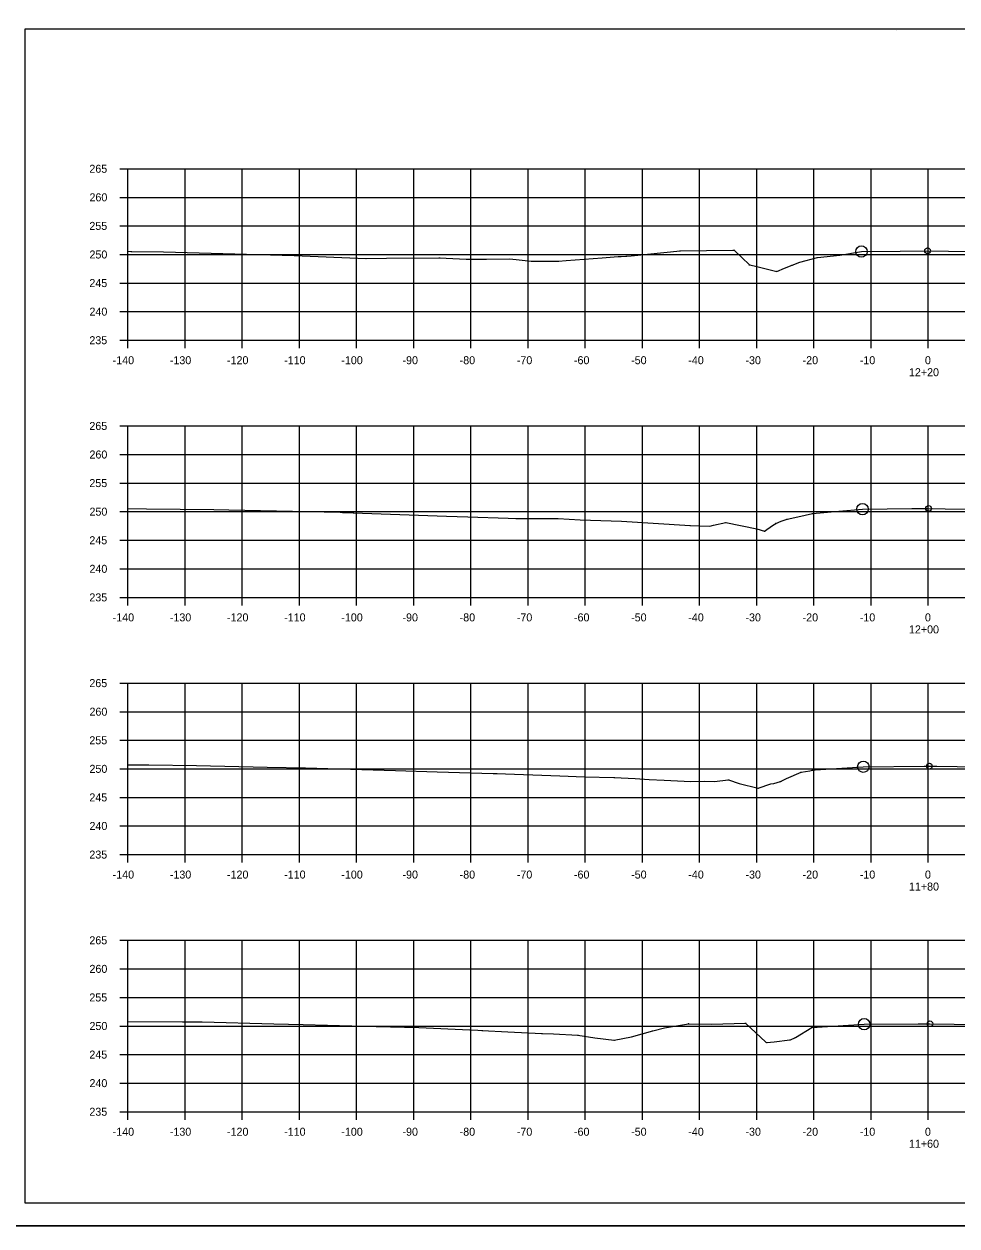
# Model space of a CAD drawing. Extents: x 1300404 to 1323571, y 234004 to 252077.
# Drawn here: x 1315559.1 to 1315722.3, y 243835.2 to 244045.5 of the extents above; entities that cross this region are included whole.
import ezdxf

# ---------------------------------------------------------------- set-up
doc = ezdxf.new("R2010")
doc.units = 0
for name, color, linetype in [('Default', 7, 'Continuous'), ('R_Axis', 7, 'Continuous'), ('R_Axis Annot', 7, 'Continuous'), ('R_Border', 7, 'Continuous'), ('R_Draft', 7, 'Continuous'), ('R_Exist Surface', 7, 'Continuous'), ('R_Grid', 7, 'Continuous'), ('R_No Plot', 7, 'Continuous')]:
    doc.layers.add(name, color=color, linetype=linetype)

msp = doc.modelspace()

# ---------------------------------------------------------------- linework, layer by layer
at = {"layer": 'Default'}
for p, q in [((1315559.28, 244044.61), (1315875.46, 244044.61)), ((1315559.28, 243839.15), (1315559.28, 244044.61)), ((1315875.46, 243839.15), (1315559.28, 243839.15))]:
    msp.add_line(p, q, dxfattribs=at)
at = {"layer": 'R_Axis'}
for p, q in [((1315575.88, 244020.15), (1315577.28, 244020.15)), ((1315577.28, 243990.15), (1315577.28, 244020.15)), ((1315575.88, 244015.15), (1315577.28, 244015.15)), ((1315575.88, 244010.15), (1315577.28, 244010.15)), ((1315575.88, 244005.15), (1315577.28, 244005.15)), ((1315575.88, 244000.15), (1315577.28, 244000.15)), ((1315575.88, 243995.15), (1315577.28, 243995.15)), ((1315575.88, 243990.15), (1315577.28, 243990.15)), ((1315577.28, 243990.15), (1315857.28, 243990.15)), ((1315577.28, 243988.75), (1315577.28, 243990.15)), ((1315587.28, 243988.75), (1315587.28, 243990.15)), ((1315597.28, 243988.75), (1315597.28, 243990.15)), ((1315607.28, 243988.75), (1315607.28, 243990.15)), ((1315617.28, 243988.75), (1315617.28, 243990.15)), ((1315627.28, 243988.75), (1315627.28, 243990.15)), ((1315637.28, 243988.75), (1315637.28, 243990.15)), ((1315647.28, 243988.75), (1315647.28, 243990.15)), ((1315657.28, 243988.75), (1315657.28, 243990.15)), ((1315667.28, 243988.75), (1315667.28, 243990.15)), ((1315677.28, 243988.75), (1315677.28, 243990.15)), ((1315687.28, 243988.75), (1315687.28, 243990.15)), ((1315697.28, 243988.75), (1315697.28, 243990.15)), ((1315707.28, 243988.75), (1315707.28, 243990.15)), ((1315717.28, 243988.75), (1315717.28, 243990.15)), ((1315575.88, 243975.15), (1315577.28, 243975.15)), ((1315577.28, 243945.15), (1315577.28, 243975.15)), ((1315575.88, 243970.15), (1315577.28, 243970.15)), ((1315575.88, 243965.15), (1315577.28, 243965.15)), ((1315575.88, 243960.15), (1315577.28, 243960.15)), ((1315575.88, 243955.15), (1315577.28, 243955.15)), ((1315575.88, 243950.15), (1315577.28, 243950.15)), ((1315575.88, 243945.15), (1315577.28, 243945.15)), ((1315577.28, 243945.15), (1315857.28, 243945.15)), ((1315577.28, 243943.75), (1315577.28, 243945.15)), ((1315587.28, 243943.75), (1315587.28, 243945.15)), ((1315597.28, 243943.75), (1315597.28, 243945.15)), ((1315607.28, 243943.75), (1315607.28, 243945.15)), ((1315617.28, 243943.75), (1315617.28, 243945.15)), ((1315627.28, 243943.75), (1315627.28, 243945.15)), ((1315637.28, 243943.75), (1315637.28, 243945.15)), ((1315647.28, 243943.75), (1315647.28, 243945.15)), ((1315657.28, 243943.75), (1315657.28, 243945.15)), ((1315667.28, 243943.75), (1315667.28, 243945.15)), ((1315677.28, 243943.75), (1315677.28, 243945.15)), ((1315687.28, 243943.75), (1315687.28, 243945.15)), ((1315697.28, 243943.75), (1315697.28, 243945.15)), ((1315707.28, 243943.75), (1315707.28, 243945.15)), ((1315717.28, 243943.75), (1315717.28, 243945.15)), ((1315575.88, 243930.15), (1315577.28, 243930.15)), ((1315577.28, 243900.15), (1315577.28, 243930.15)), ((1315575.88, 243925.15), (1315577.28, 243925.15)), ((1315575.88, 243920.15), (1315577.28, 243920.15)), ((1315575.88, 243915.15), (1315577.28, 243915.15)), ((1315575.88, 243910.15), (1315577.28, 243910.15)), ((1315575.88, 243905.15), (1315577.28, 243905.15)), ((1315575.88, 243900.15), (1315577.28, 243900.15)), ((1315577.28, 243900.15), (1315857.28, 243900.15)), ((1315577.28, 243898.75), (1315577.28, 243900.15)), ((1315587.28, 243898.75), (1315587.28, 243900.15)), ((1315597.28, 243898.75), (1315597.28, 243900.15)), ((1315607.28, 243898.75), (1315607.28, 243900.15)), ((1315617.28, 243898.75), (1315617.28, 243900.15)), ((1315627.28, 243898.75), (1315627.28, 243900.15)), ((1315637.28, 243898.75), (1315637.28, 243900.15)), ((1315647.28, 243898.75), (1315647.28, 243900.15)), ((1315657.28, 243898.75), (1315657.28, 243900.15)), ((1315667.28, 243898.75), (1315667.28, 243900.15)), ((1315677.28, 243898.75), (1315677.28, 243900.15)), ((1315687.28, 243898.75), (1315687.28, 243900.15)), ((1315697.28, 243898.75), (1315697.28, 243900.15)), ((1315707.28, 243898.75), (1315707.28, 243900.15)), ((1315717.28, 243898.75), (1315717.28, 243900.15)), ((1315575.88, 243885.15), (1315577.28, 243885.15)), ((1315577.28, 243855.15), (1315577.28, 243885.15)), ((1315575.88, 243880.15), (1315577.28, 243880.15)), ((1315575.88, 243875.15), (1315577.28, 243875.15)), ((1315575.88, 243870.15), (1315577.28, 243870.15)), ((1315575.88, 243865.15), (1315577.28, 243865.15)), ((1315575.88, 243860.15), (1315577.28, 243860.15)), ((1315575.88, 243855.15), (1315577.28, 243855.15)), ((1315577.28, 243855.15), (1315857.28, 243855.15)), ((1315577.28, 243853.75), (1315577.28, 243855.15)), ((1315587.28, 243853.75), (1315587.28, 243855.15)), ((1315597.28, 243853.75), (1315597.28, 243855.15)), ((1315607.28, 243853.75), (1315607.28, 243855.15)), ((1315617.28, 243853.75), (1315617.28, 243855.15)), ((1315627.28, 243853.75), (1315627.28, 243855.15)), ((1315637.28, 243853.75), (1315637.28, 243855.15)), ((1315647.28, 243853.75), (1315647.28, 243855.15)), ((1315657.28, 243853.75), (1315657.28, 243855.15)), ((1315667.28, 243853.75), (1315667.28, 243855.15)), ((1315677.28, 243853.75), (1315677.28, 243855.15)), ((1315687.28, 243853.75), (1315687.28, 243855.15)), ((1315697.28, 243853.75), (1315697.28, 243855.15)), ((1315707.28, 243853.75), (1315707.28, 243855.15)), ((1315717.28, 243853.75), (1315717.28, 243855.15))]:
    msp.add_line(p, q, dxfattribs=at)
at = {"layer": 'R_Border'}
for p, q in [((1315711.8, 244044.35), (1315711.8, 244044.35)), ((1315711.8, 244044.35), (1315711.8, 244044.35)), ((1315559.28, 243839.15), (1315559.28, 243839.15))]:
    msp.add_line(p, q, dxfattribs=at)
at = {"layer": 'R_Draft'}
for points in [[(1315577.86, 244005.73), (1315577.91, 244005.63), (1315577.81, 244005.63)], [(1315618.92, 244004.49), (1315618.97, 244004.39), (1315618.87, 244004.39)], [(1315631.78, 244004.63), (1315631.83, 244004.53), (1315631.73, 244004.53)], [(1315664.49, 244004.9), (1315664.54, 244004.8), (1315664.44, 244004.8)], [(1315673.91, 244005.82), (1315673.96, 244005.72), (1315673.86, 244005.72)], [(1315683.31, 244005.97), (1315683.36, 244005.87), (1315683.26, 244005.87)], [(1315697.89, 244004.69), (1315697.94, 244004.59), (1315697.84, 244004.59)], [(1315647.86, 244004.04), (1315647.91, 244003.94), (1315647.81, 244003.94)], [(1315652.61, 244004.05), (1315652.66, 244003.95), (1315652.56, 244003.95)], [(1315686.01, 244003.39), (1315686.06, 244003.29), (1315685.96, 244003.29)], [(1315693.49, 244003.33), (1315693.54, 244003.23), (1315693.44, 244003.23)], [(1315690.79, 244002.25), (1315690.84, 244002.15), (1315690.74, 244002.15)], [(1315616.69, 243960.02), (1315616.74, 243959.92), (1315616.64, 243959.92)], [(1315646.06, 243959.01), (1315646.11, 243958.91), (1315646.01, 243958.91)], [(1315681.86, 243958.28), (1315681.91, 243958.18), (1315681.81, 243958.18)], [(1315692.6, 243958.89), (1315692.65, 243958.79), (1315692.55, 243958.79)], [(1315697.02, 243959.85), (1315697.07, 243959.75), (1315696.97, 243959.75)], [(1315675.64, 243957.75), (1315675.69, 243957.65), (1315675.59, 243957.65)], [(1315688.63, 243956.78), (1315688.68, 243956.68), (1315688.58, 243956.68)], [(1315690.64, 243958.15), (1315690.69, 243958.05), (1315690.59, 243958.05)], [(1315641.75, 243914.37), (1315641.8, 243914.27), (1315641.7, 243914.27)], [(1315695.04, 243914.63), (1315695.09, 243914.53), (1315694.99, 243914.53)], [(1315697.02, 243914.98), (1315697.07, 243914.88), (1315696.97, 243914.88)], [(1315662.33, 243913.7), (1315662.38, 243913.6), (1315662.28, 243913.6)], [(1315682.35, 243913.29), (1315682.4, 243913.19), (1315682.3, 243913.19)], [(1315691.46, 243912.99), (1315691.51, 243912.89), (1315691.41, 243912.89)], [(1315687.53, 243911.79), (1315687.58, 243911.69), (1315687.48, 243911.69)], [(1315675.36, 243870.61), (1315675.41, 243870.51), (1315675.31, 243870.51)], [(1315685.3, 243870.69), (1315685.35, 243870.59), (1315685.25, 243870.59)], [(1315696.92, 243869.93), (1315696.97, 243869.83), (1315696.87, 243869.83)], [(1315639.25, 243869.43), (1315639.3, 243869.33), (1315639.2, 243869.33)], [(1315649.68, 243868.87), (1315649.73, 243868.77), (1315649.63, 243868.77)], [(1315656, 243868.6), (1315656.05, 243868.5), (1315655.95, 243868.5)], [(1315669.08, 243869.36), (1315669.13, 243869.26), (1315669.03, 243869.26)], [(1315693.07, 243867.76), (1315693.12, 243867.66), (1315693.02, 243867.66)], [(1315694.08, 243868.18), (1315694.13, 243868.08), (1315694.03, 243868.08)], [(1315662.34, 243867.7), (1315662.39, 243867.6), (1315662.29, 243867.6)], [(1315689.05, 243867.29), (1315689.1, 243867.19), (1315689, 243867.19)]]:
    msp.add_lwpolyline(points, close=True, dxfattribs=at)
at = {"layer": 'R_Exist Surface'}
for points in [[(1315577.28, 244005.74), (1315577.86, 244005.68), (1315583.52, 244005.59), (1315606.38, 244004.98), (1315618.92, 244004.44), (1315622.54, 244004.5), (1315631.78, 244004.58), (1315636.45, 244004.34), (1315639.98, 244004.33), (1315644.08, 244004.37), (1315647.86, 244003.99), (1315651.37, 244004.01), (1315652.61, 244004), (1315653.92, 244004.1), (1315660.25, 244004.57), (1315663.05, 244004.77), (1315663.56, 244004.78), (1315664.49, 244004.85), (1315665.29, 244004.93), (1315673.91, 244005.77), (1315683.08, 244005.92), (1315683.22, 244005.92), (1315683.31, 244005.92), (1315683.35, 244005.91), (1315686.01, 244003.34), (1315686.83, 244003.17), (1315690.79, 244002.2), (1315692.14, 244002.74), (1315693.49, 244003.28), (1315694.83, 244003.79), (1315697.89, 244004.64), (1315701.8, 244005.05), (1315705.6, 244005.66), (1315712.38, 244005.74), (1315717.17, 244005.81), (1315724.49, 244005.7)], [(1315577.28, 243960.72), (1315580.53, 243960.67), (1315592.3, 243960.51), (1315594.95, 243960.45), (1315614.41, 243960.05), (1315614.84, 243960.03), (1315616.69, 243959.97), (1315633, 243959.36), (1315636.75, 243959.26), (1315643.81, 243959), (1315645.11, 243958.97), (1315646.06, 243958.96), (1315652.54, 243958.94), (1315656.39, 243958.73), (1315663.65, 243958.46), (1315675.64, 243957.7), (1315677.18, 243957.65), (1315679.06, 243957.6), (1315679.72, 243957.77), (1315681.86, 243958.23), (1315687.3, 243957.16), (1315688.63, 243956.73), (1315690.03, 243957.7), (1315690.64, 243958.1), (1315691.57, 243958.46), (1315692.6, 243958.84), (1315694.45, 243959.22), (1315697.02, 243959.8), (1315701.65, 243960.26), (1315705.79, 243960.58), (1315714.41, 243960.68), (1315717.35, 243960.71), (1315720.25, 243960.67), (1315729.39, 243960.54)], [(1315577.28, 243915.87), (1315580.94, 243915.87), (1315589.26, 243915.76), (1315601.65, 243915.45), (1315608.36, 243915.31), (1315624.07, 243914.88), (1315631.4, 243914.64), (1315641.17, 243914.33), (1315641.75, 243914.32), (1315652.86, 243913.9), (1315657.17, 243913.78), (1315662.33, 243913.65), (1315666.01, 243913.44), (1315668.45, 243913.3), (1315671.1, 243913.18), (1315675.76, 243912.91), (1315678.21, 243912.98), (1315679.85, 243912.93), (1315682.35, 243913.24), (1315684.23, 243912.61), (1315687.53, 243911.74), (1315689.73, 243912.53), (1315690.25, 243912.56), (1315691.46, 243912.94), (1315692.48, 243913.45), (1315695.04, 243914.58), (1315696.57, 243914.83), (1315697.02, 243914.93), (1315697.52, 243914.97), (1315705.93, 243915.52), (1315716.6, 243915.61), (1315717.48, 243915.62), (1315718.79, 243915.6), (1315729.5, 243915.44)], [(1315577.28, 243870.96), (1315586.83, 243870.87), (1315590.24, 243870.88), (1315602.82, 243870.56), (1315607.92, 243870.42), (1315620.72, 243870.07), (1315628.18, 243869.87), (1315637.1, 243869.46), (1315638.5, 243869.4), (1315639.25, 243869.38), (1315643.76, 243869.16), (1315649.68, 243868.82), (1315651.74, 243868.77), (1315656, 243868.55), (1315658.97, 243868.06), (1315662.34, 243867.65), (1315665.4, 243868.28), (1315669.08, 243869.31), (1315671.17, 243869.81), (1315675.36, 243870.56), (1315679.37, 243870.46), (1315685.3, 243870.64), (1315688.9, 243867.34), (1315689.05, 243867.24), (1315690.34, 243867.39), (1315693.07, 243867.71), (1315693.19, 243867.75), (1315694.08, 243868.13), (1315696.91, 243869.87), (1315696.92, 243869.88), (1315696.95, 243869.88), (1315706.07, 243870.46), (1315715.51, 243870.53), (1315717.59, 243870.55), (1315721.8, 243870.48), (1315729.53, 243870.36)]]:
    msp.add_lwpolyline(points, dxfattribs=at)
at = {"layer": 'R_Grid'}
for p, q in [((1315577.28, 244020.15), (1315857.28, 244020.15)), ((1315577.28, 243990.15), (1315577.28, 244020.15)), ((1315587.28, 243990.15), (1315587.28, 244020.15)), ((1315597.28, 243990.15), (1315597.28, 244020.15)), ((1315607.28, 243990.15), (1315607.28, 244020.15)), ((1315617.28, 243990.15), (1315617.28, 244020.15)), ((1315627.28, 243990.15), (1315627.28, 244020.15)), ((1315637.28, 243990.15), (1315637.28, 244020.15)), ((1315647.28, 243990.15), (1315647.28, 244020.15)), ((1315657.28, 243990.15), (1315657.28, 244020.15)), ((1315667.28, 243990.15), (1315667.28, 244020.15)), ((1315677.28, 243990.15), (1315677.28, 244020.15)), ((1315687.28, 243990.15), (1315687.28, 244020.15)), ((1315697.28, 243990.15), (1315697.28, 244020.15)), ((1315707.28, 243990.15), (1315707.28, 244020.15)), ((1315717.28, 243990.15), (1315717.28, 244020.15)), ((1315577.28, 244015.15), (1315857.28, 244015.15)), ((1315577.28, 244010.15), (1315857.28, 244010.15)), ((1315577.28, 244005.15), (1315857.28, 244005.15)), ((1315577.28, 244000.15), (1315857.28, 244000.15)), ((1315577.28, 243995.15), (1315857.28, 243995.15)), ((1315577.28, 243990.15), (1315857.28, 243990.15)), ((1315577.28, 243975.15), (1315857.28, 243975.15)), ((1315577.28, 243945.15), (1315577.28, 243975.15)), ((1315587.28, 243945.15), (1315587.28, 243975.15)), ((1315597.28, 243945.15), (1315597.28, 243975.15)), ((1315607.28, 243945.15), (1315607.28, 243975.15)), ((1315617.28, 243945.15), (1315617.28, 243975.15)), ((1315627.28, 243945.15), (1315627.28, 243975.15)), ((1315637.28, 243945.15), (1315637.28, 243975.15)), ((1315647.28, 243945.15), (1315647.28, 243975.15)), ((1315657.28, 243945.15), (1315657.28, 243975.15)), ((1315667.28, 243945.15), (1315667.28, 243975.15)), ((1315677.28, 243945.15), (1315677.28, 243975.15)), ((1315687.28, 243945.15), (1315687.28, 243975.15)), ((1315697.28, 243945.15), (1315697.28, 243975.15)), ((1315707.28, 243945.15), (1315707.28, 243975.15)), ((1315717.28, 243945.15), (1315717.28, 243975.15)), ((1315577.28, 243970.15), (1315857.28, 243970.15)), ((1315577.28, 243965.15), (1315857.28, 243965.15)), ((1315577.28, 243960.15), (1315857.28, 243960.15)), ((1315577.28, 243955.15), (1315857.28, 243955.15)), ((1315577.28, 243950.15), (1315857.28, 243950.15)), ((1315577.28, 243945.15), (1315857.28, 243945.15)), ((1315577.28, 243930.15), (1315857.28, 243930.15)), ((1315577.28, 243900.15), (1315577.28, 243930.15)), ((1315587.28, 243900.15), (1315587.28, 243930.15)), ((1315597.28, 243900.15), (1315597.28, 243930.15)), ((1315607.28, 243900.15), (1315607.28, 243930.15)), ((1315617.28, 243900.15), (1315617.28, 243930.15)), ((1315627.28, 243900.15), (1315627.28, 243930.15)), ((1315637.28, 243900.15), (1315637.28, 243930.15)), ((1315647.28, 243900.15), (1315647.28, 243930.15)), ((1315657.28, 243900.15), (1315657.28, 243930.15)), ((1315667.28, 243900.15), (1315667.28, 243930.15)), ((1315677.28, 243900.15), (1315677.28, 243930.15)), ((1315687.28, 243900.15), (1315687.28, 243930.15)), ((1315697.28, 243900.15), (1315697.28, 243930.15)), ((1315707.28, 243900.15), (1315707.28, 243930.15)), ((1315717.28, 243900.15), (1315717.28, 243930.15)), ((1315577.28, 243925.15), (1315857.28, 243925.15)), ((1315577.28, 243920.15), (1315857.28, 243920.15)), ((1315577.28, 243915.15), (1315857.28, 243915.15)), ((1315577.28, 243910.15), (1315857.28, 243910.15)), ((1315577.28, 243905.15), (1315857.28, 243905.15)), ((1315577.28, 243900.15), (1315857.28, 243900.15)), ((1315577.28, 243885.15), (1315857.28, 243885.15)), ((1315577.28, 243855.15), (1315577.28, 243885.15)), ((1315587.28, 243855.15), (1315587.28, 243885.15)), ((1315597.28, 243855.15), (1315597.28, 243885.15)), ((1315607.28, 243855.15), (1315607.28, 243885.15)), ((1315617.28, 243855.15), (1315617.28, 243885.15)), ((1315627.28, 243855.15), (1315627.28, 243885.15)), ((1315637.28, 243855.15), (1315637.28, 243885.15)), ((1315647.28, 243855.15), (1315647.28, 243885.15)), ((1315657.28, 243855.15), (1315657.28, 243885.15)), ((1315667.28, 243855.15), (1315667.28, 243885.15)), ((1315677.28, 243855.15), (1315677.28, 243885.15)), ((1315687.28, 243855.15), (1315687.28, 243885.15)), ((1315697.28, 243855.15), (1315697.28, 243885.15)), ((1315707.28, 243855.15), (1315707.28, 243885.15)), ((1315717.28, 243855.15), (1315717.28, 243885.15)), ((1315577.28, 243880.15), (1315857.28, 243880.15)), ((1315577.28, 243875.15), (1315857.28, 243875.15)), ((1315577.28, 243870.15), (1315857.28, 243870.15)), ((1315577.28, 243865.15), (1315857.28, 243865.15)), ((1315577.28, 243860.15), (1315857.28, 243860.15)), ((1315577.28, 243855.15), (1315857.28, 243855.15))]:
    msp.add_line(p, q, dxfattribs=at)
at = {"layer": 'R_No Plot'}
msp.add_line((1315546.87, 243835.17), (1315880.21, 243835.17), dxfattribs=at)
for points in [[(1315546.87, 244048.5), (1315880.21, 244048.5), (1315880.21, 243835.16), (1315546.87, 243835.16)], [(1315793.2, 244044.61), (1315793.2, 244034.73), (1315828.93, 244034.73), (1315828.93, 244031.81), (1315852.13, 244031.81), (1315852.13, 244009.69), (1315875.46, 244009.69), (1315875.46, 243839.15), (1315559.28, 243839.15), (1315559.28, 244044.61)]]:
    msp.add_lwpolyline(points, close=True, dxfattribs=at)
for centre, radius in [((1315705.6, 244005.66), 1), ((1315717.17, 244005.81), 0.5), ((1315705.79, 243960.58), 1), ((1315717.35, 243960.71), 0.5), ((1315705.93, 243915.52), 1), ((1315717.48, 243915.62), 0.5), ((1315706.07, 243870.46), 1), ((1315717.59, 243870.55), 0.5)]:
    msp.add_circle(centre, radius, dxfattribs=at)

# ---------------------------------------------------------------- texts
at = {"layer": 'R_Axis'}
for p in [(1315577.28, 243990.15), (1315577.28, 243945.15), (1315577.28, 243900.15), (1315577.28, 243855.15)]:
    msp.add_text('-', height=0.0001, dxfattribs=at).set_placement(p)
at = {"layer": 'R_Axis Annot'}
for s, p in [('265', (1315570.53, 244019.45)), ('260', (1315570.55, 244014.45)), ('255', (1315570.53, 244009.45)), ('250', (1315570.55, 244004.45)), ('245', (1315570.53, 243999.45)), ('240', (1315570.55, 243994.45)), ('235', (1315570.53, 243989.45)), ('-140', (1315574.61, 243985.95)), ('-130', (1315584.61, 243985.95)), ('-120', (1315594.61, 243985.95)), ('-110', (1315604.61, 243985.95)), ('-100', (1315614.61, 243985.95)), ('-90', (1315625.31, 243985.95)), ('-80', (1315635.31, 243985.95)), ('-70', (1315645.31, 243985.95)), ('-60', (1315655.31, 243985.95)), ('-50', (1315665.31, 243985.95)), ('-40', (1315675.31, 243985.95)), ('-30', (1315685.31, 243985.95)), ('-20', (1315695.31, 243985.95)), ('-10', (1315705.31, 243985.95)), ('0', (1315716.71, 243985.95)), ('12+20', (1315713.91, 243983.85)), ('265', (1315570.53, 243974.45)), ('260', (1315570.55, 243969.45)), ('255', (1315570.53, 243964.45)), ('250', (1315570.55, 243959.45)), ('245', (1315570.53, 243954.45)), ('240', (1315570.55, 243949.45)), ('235', (1315570.53, 243944.45)), ('-140', (1315574.61, 243940.95)), ('-130', (1315584.61, 243940.95)), ('-120', (1315594.61, 243940.95)), ('-110', (1315604.61, 243940.95)), ('-100', (1315614.61, 243940.95)), ('-90', (1315625.31, 243940.95)), ('-80', (1315635.31, 243940.95)), ('-70', (1315645.31, 243940.95)), ('-60', (1315655.31, 243940.95)), ('-50', (1315665.31, 243940.95)), ('-40', (1315675.31, 243940.95)), ('-30', (1315685.31, 243940.95)), ('-20', (1315695.31, 243940.95)), ('-10', (1315705.31, 243940.95)), ('0', (1315716.71, 243940.95)), ('12+00', (1315713.91, 243938.85)), ('265', (1315570.53, 243929.45)), ('260', (1315570.55, 243924.45)), ('255', (1315570.53, 243919.45)), ('250', (1315570.55, 243914.45)), ('245', (1315570.53, 243909.45)), ('240', (1315570.55, 243904.45)), ('235', (1315570.53, 243899.45)), ('-140', (1315574.61, 243895.95)), ('-130', (1315584.61, 243895.95)), ('-120', (1315594.61, 243895.95)), ('-110', (1315604.61, 243895.95)), ('-100', (1315614.61, 243895.95)), ('-90', (1315625.31, 243895.95)), ('-80', (1315635.31, 243895.95)), ('-70', (1315645.31, 243895.95)), ('-60', (1315655.31, 243895.95)), ('-50', (1315665.31, 243895.95)), ('-40', (1315675.31, 243895.95)), ('-30', (1315685.31, 243895.95)), ('-20', (1315695.31, 243895.95)), ('-10', (1315705.31, 243895.95)), ('0', (1315716.71, 243895.95)), ('11+80', (1315713.91, 243893.85)), ('265', (1315570.53, 243884.45)), ('260', (1315570.55, 243879.45)), ('255', (1315570.53, 243874.45)), ('250', (1315570.55, 243869.45)), ('245', (1315570.53, 243864.45)), ('240', (1315570.55, 243859.45)), ('235', (1315570.53, 243854.45)), ('-140', (1315574.61, 243850.95)), ('-130', (1315584.61, 243850.95)), ('-120', (1315594.61, 243850.95)), ('-110', (1315604.61, 243850.95)), ('-100', (1315614.61, 243850.95)), ('-90', (1315625.31, 243850.95)), ('-80', (1315635.31, 243850.95)), ('-70', (1315645.31, 243850.95)), ('-60', (1315655.31, 243850.95)), ('-50', (1315665.31, 243850.95)), ('-40', (1315675.31, 243850.95)), ('-30', (1315685.31, 243850.95)), ('-20', (1315695.31, 243850.95)), ('-10', (1315705.31, 243850.95)), ('0', (1315716.71, 243850.95)), ('11+60', (1315713.91, 243848.85))]:
    msp.add_text(s, height=1.4, dxfattribs=at).set_placement(p)

doc.saveas('drawing.dxf')
